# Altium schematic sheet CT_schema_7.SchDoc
size 278 x 170 mm
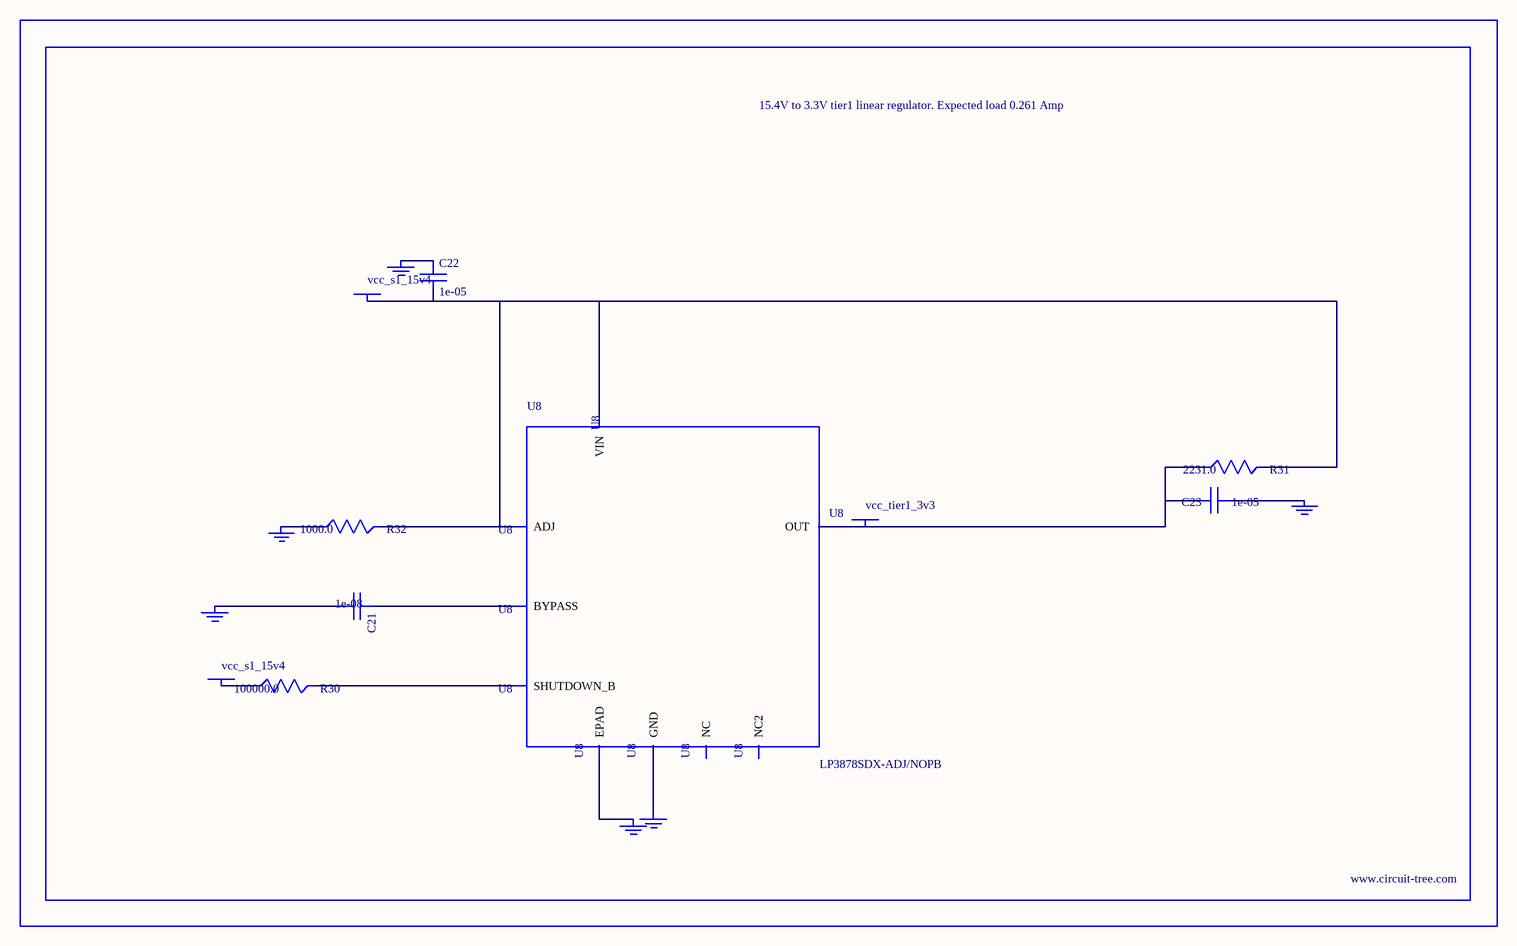
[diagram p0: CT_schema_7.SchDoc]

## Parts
BORDER6  (no value)
C21  1e-08  [C0402]
C22  1e-05  [C1210]
C23  1e-05  [C1210]
GND_INSTANCE_6_0  (no value)
GND_INSTANCE_6_1  (no value)
GND_INSTANCE_6_2  (no value)
GND_INSTANCE_6_3  (no value)
GND_INSTANCE_6_4  (no value)
GND_INSTANCE_6_5  (no value)
POWER_INSTANCE_6_0  vcc_s1_15v4
POWER_INSTANCE_6_1  vcc_s1_15v4
POWER_INSTANCE_6_2  vcc_tier1_3v3
R30  100000.0  [R0603]
R31  2231.0  [R0603]
R32  1000.0  [R0603]
U8  LP3878SDX-ADJ/NOPB  [WSON-8]

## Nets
NetC21_1: C21.1 U8.1(BYPASS)
NetC21_2: C21.2 GND_INSTANCE_6_0.0(GND)
NetC22_1: C22.1 GND_INSTANCE_6_1.0(GND)
NetC22_2: C22.2 POWER_INSTANCE_6_0.0(PWR) R31.2 R32.2 U8.4(VIN) U8.6(ADJ)
NetC23_1: C23.1 GND_INSTANCE_6_2.0(GND)
NetC23_2: C23.2 POWER_INSTANCE_6_2.0(PWR) R31.1 U8.5(OUT)
NetGND_INSTANCE_6_3_0: GND_INSTANCE_6_3.0(GND) R32.1
NetGND_INSTANCE_6_4_0: GND_INSTANCE_6_4.0(GND) U8.PAD(EPAD)
NetGND_INSTANCE_6_5_0: GND_INSTANCE_6_5.0(GND) U8.3(GND)
NetPOWER_INSTANCE_6_1_0: POWER_INSTANCE_6_1.0(PWR) R30.1
NetR30_2: R30.2 U8.8(SHUTDOWN_B)

Not connected (* = marked no-connect by the designer): U8 2(NC) 7(NC2)

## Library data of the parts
BORDER6 = BORDER_PAGE6
C21 = C0402C103K3RAC
C22 = C1210C106K5PACTU
C23 = GRM32DR61E106MA12L
GND_INSTANCE_6_0-GND_INSTANCE_6_5 = GND
POWER_INSTANCE_6_0-POWER_INSTANCE_6_2 = PWR
R30 = RC0603JR-07100KL
R31 = R31
R32 = RC0603JR-071KL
